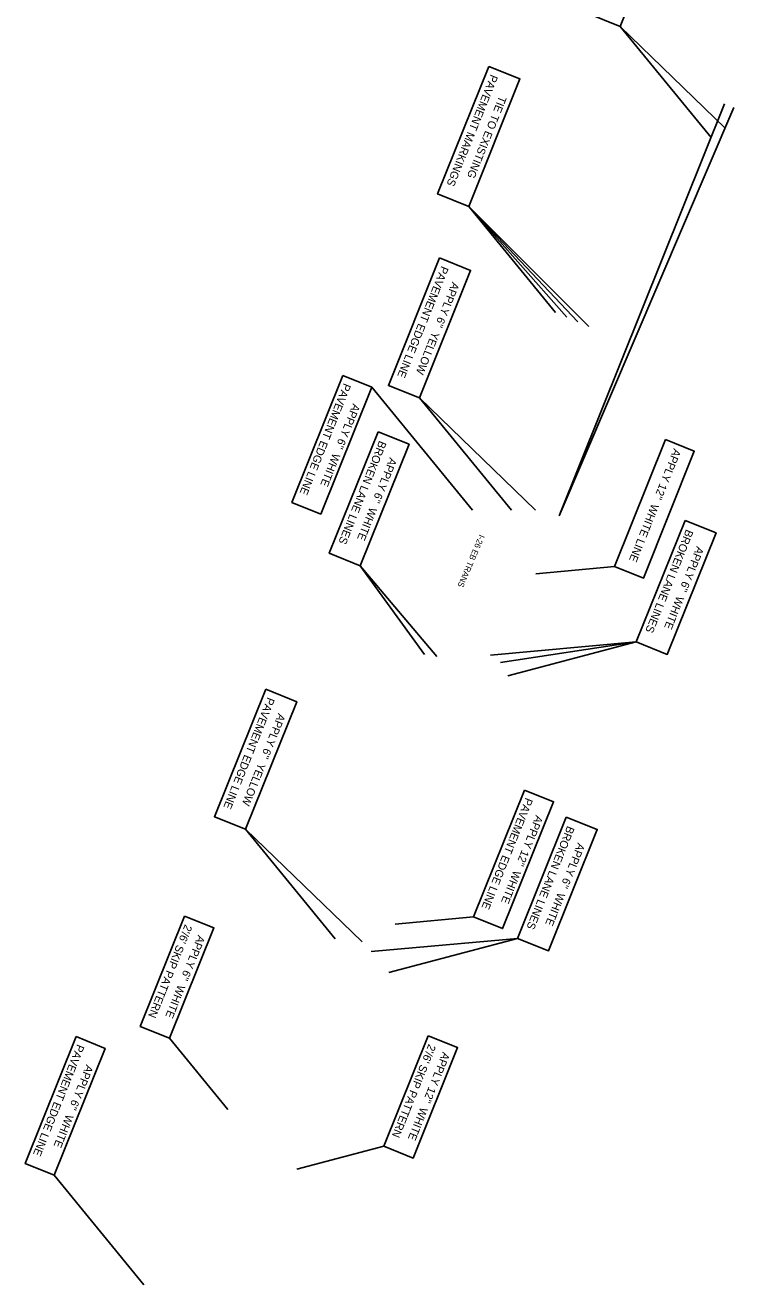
# Model space of a CAD drawing. Extents: x 1966013 to 1974896, y 789499 to 804826.
# Drawn here: x 1967351 to 1968059, y 794265 to 795524 of the extents above; entities that cross this region are included whole.
import ezdxf

# ---------------------------------------------------------------- set-up
doc = ezdxf.new("R2010")
doc.units = 0
for name, color, linetype in [('RD_EX_H2O_BlueLn', 7, 'Continuous'), ('RD_PD_Final_LnLine', 7, 'Continuous'), ('RD_PD_MedBWall', 7, 'Continuous')]:
    doc.layers.add(name, color=color, linetype=linetype)

msp = doc.modelspace()

# ---------------------------------------------------------------- linework, layer by layer
at = {"layer": 'RD_EX_H2O_BlueLn'}
for p, q in [((1967945.5, 795523.1), (1968036.4, 795412.2)), ((1967945.5, 795523.1), (1968050.4, 795421.6)), ((1967794.2, 795343.3), (1967881, 795237.4)), ((1967794.2, 795343.3), (1967892.1, 795232.7)), ((1967794.2, 795343.3), (1967903.1, 795228.1)), ((1967794.2, 795343.3), (1967914.2, 795223.4)), ((1967697.2, 795162.6), (1967797.8, 795039.8)), ((1967744.9, 795151.9), (1967836.8, 795039.7)), ((1967744.9, 795151.9), (1967860.9, 795039.7)), ((1967685.8, 794984.2), (1967762.3, 794893.6)), ((1967685.8, 794984.2), (1967750, 794895.4)), ((1967861.3, 794976.2), (1967939.9, 794983.3)), ((1967816, 794894.9), (1967961.6, 794908)), ((1967825.8, 794887.5), (1967961.6, 794908)), ((1967833.2, 794874.1), (1967961.6, 794908)), ((1967571.1, 794720.8), (1967660.8, 794611.3)), ((1967571.1, 794720.8), (1967687.6, 794608.1)), ((1967720.6, 794626), (1967799.1, 794633.1)), ((1967696.6, 794598.5), (1967842.8, 794611.6)), ((1967714.2, 794577.7), (1967842.8, 794611.6)), ((1967495.1, 794511.9), (1967553.4, 794440.7)), ((1967622.2, 794381), (1967709.4, 794404)), ((1967379.7, 794375), (1967469.5, 794265.5))]:
    msp.add_line(p, q, dxfattribs=at)
for points in [[(1967967.8, 795674.2), (1967912.5, 795536.3), (1967945.5, 795523.1), (1968000.8, 795660.9)], [(1967814.3, 795483.2), (1967763.1, 795355.8), (1967794.2, 795343.3), (1967845.4, 795470.7)], [(1967765.1, 795291.8), (1967713.9, 795164.3), (1967744.9, 795151.9), (1967796.1, 795279.3)], [(1967668.3, 795174.2), (1967617.4, 795047.4), (1967646.3, 795035.8), (1967697.2, 795162.6)], [(1967703.5, 795118.1), (1967654.8, 794996.7), (1967685.8, 794984.2), (1967734.6, 795105.6)], [(1967990.8, 795110.2), (1967939.9, 794983.3), (1967968.8, 794971.7), (1968019.7, 795098.6)], [(1968010.4, 795029.4), (1967961.6, 794908), (1967992.7, 794895.6), (1968041.4, 795016.9)], [(1967591.2, 794860.7), (1967540, 794733.3), (1967571.1, 794720.8), (1967622.2, 794848.3)], [(1967850, 794760), (1967799.1, 794633.1), (1967828, 794621.5), (1967879, 794748.3)], [(1967891.5, 794733), (1967842.8, 794611.6), (1967873.8, 794599.2), (1967922.6, 794720.6)], [(1967510.1, 794634), (1967465.8, 794523.7), (1967495.1, 794511.9), (1967539.4, 794622.2)], [(1967401.7, 794513.5), (1967350.8, 794386.6), (1967379.7, 794375), (1967430.7, 794501.8)], [(1967753.7, 794514.4), (1967709.4, 794404), (1967738.7, 794392.2), (1967783, 794502.6)]]:
    msp.add_lwpolyline(points, close=True, dxfattribs=at)
at = {"layer": 'RD_PD_Final_LnLine'}
for p in [(1968049.9, 795446), (1968059.2, 795442.2)]:
    msp.add_line(p, (1967884.5, 795034), dxfattribs=at)

# ---------------------------------------------------------------- texts
at = {"layer": 'RD_EX_H2O_BlueLn'}
for s, height, rotation, p in [('PAVEMENT MARKINGS', 8, 248.119, (1967816.2, 795475.8)), ('TIE TO EXISTING', 8, 248.119, (1967824.8, 795454.3)), ('PAVEMENT EDGE LINE', 8, 248.119, (1967766.9, 795284.3)), ("APPLY 6''  YELLOW", 8, 248.119, (1967777.7, 795268.3)), ('PAVEMENT EDGE LINE', 8, 248.119, (1967669.3, 795167.2)), ("APPLY 6''  WHITE", 8, 248.119, (1967678.4, 795146.8)), ('BROKEN LANE LINES', 8, 248.119, (1967704.8, 795109.7)), ("APPLY 12''  WHITE LINE", 8, 248.119, (1967999.2, 795101.8)), ("APPLY 6''  WHITE", 8, 248.119, (1967715.2, 795092.8)), ('BROKEN LANE LINES', 8, 248.119, (1968011.6, 795021.1)), ("APPLY 6''  WHITE", 8, 248.119, (1968022.1, 795004.1)), ('PAVEMENT EDGE LINE', 8, 248.119, (1967593.1, 794853.3)), ("APPLY 6''  YELLOW", 8, 248.119, (1967603.8, 794837.2)), ('PAVEMENT EDGE LINE', 8, 248.119, (1967851.1, 794752.9)), ("APPLY 12''  WHITE", 8, 248.119, (1967861.3, 794735.4)), ('BROKEN LANE LINES', 8, 248.119, (1967892.8, 794724.7)), ("APPLY 6''  WHITE", 8, 248.119, (1967903.2, 794707.7)), ("2'/6' SKIP PATTERN", 7.999, 248.1009, (1967510.6, 794626.2)), ("APPLY 6''  WHITE", 7.999, 248.1009, (1967523.5, 794615.5)), ('PAVEMENT EDGE LINE', 8, 248.119, (1967402.8, 794506.4)), ("2'/6' SKIP PATTERN", 7.999, 248.1009, (1967754.2, 794506.6)), ("APPLY 12''  WHITE", 7.999, 248.1009, (1967768.2, 794498.7)), ("APPLY 6''  WHITE", 8, 248.119, (1967411.8, 794486))]:
    msp.add_text(s, height=height, rotation=rotation, dxfattribs=at).set_placement(p)
at = {"layer": 'RD_PD_MedBWall'}
msp.add_text('I-26 EB TRANS', height=6, rotation=247.071, dxfattribs=at).set_placement((1967804.8, 795015.9))

doc.saveas('drawing.dxf')
